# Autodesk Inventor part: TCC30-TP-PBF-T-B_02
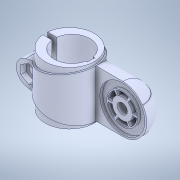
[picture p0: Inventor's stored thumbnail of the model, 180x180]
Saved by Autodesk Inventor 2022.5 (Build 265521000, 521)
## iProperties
Created: 2023-09
Part Number: TCC30-TP-PBF-T-B_02
Material: 一般
Document SubType Name: Modeling
Designer: ImaoCorp
Density: 1 g/cm^3
Appearance: 既定
Author: ImaoCorp
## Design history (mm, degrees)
feature "TCC30-TP-PBF-T-B_02"
node "ソリッド1"
